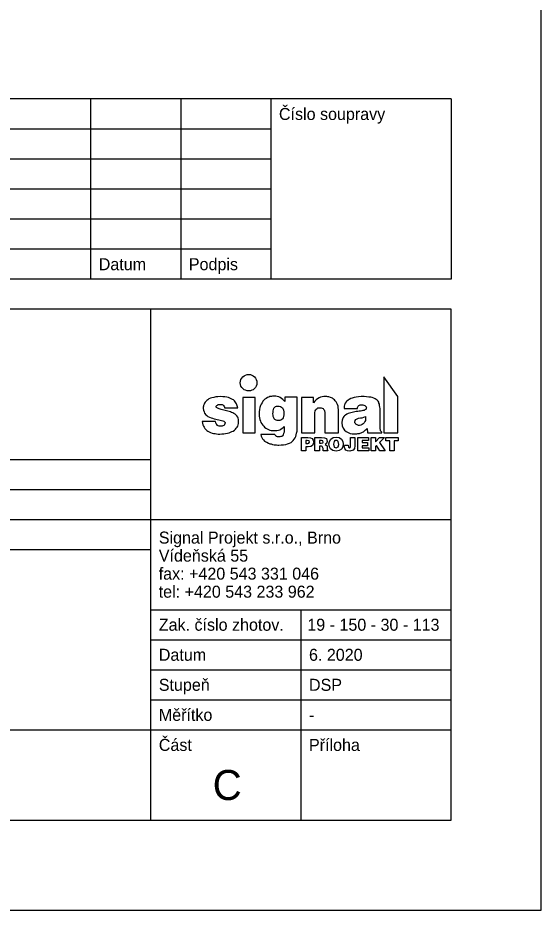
# Model space of a CAD drawing. Extents: x -790471 to -790261, y -985260 to -984963.
# Drawn here: x -790347.7 to -790260.6, y -985259.6 to -985111.1 of the extents above; entities that cross this region are included whole.
import ezdxf

# ---------------------------------------------------------------- set-up
doc = ezdxf.new("R2010")
doc.units = 0
for name, color, linetype in [('Info o rozpiskách', 7, 'Continuous'), ('popis', 7, 'Continuous'), ('Ramečky', 7, 'Continuous'), ('Rámečky-tisk', 7, 'Continuous'), ('Text', 7, 'Continuous'), ('Text barevný', 7, 'Continuous')]:
    doc.layers.add(name, color=color, linetype=linetype)

msp = doc.modelspace()

# ---------------------------------------------------------------- linework, layer by layer
at = {"layer": 'Info o rozpiskách'}
for points in [[(-790309.25, -985170.46), (-790308.98, -985170.47), (-790308.76, -985170.57), (-790308.54, -985170.7), (-790308.29, -985170.87), (-790308.15, -985171.07), (-790308.03, -985171.31), (-790307.94, -985171.58), (-790307.92, -985171.84), (-790307.94, -985172.1), (-790308.03, -985172.38), (-790308.15, -985172.62), (-790308.29, -985172.79), (-790308.54, -985172.99), (-790308.76, -985173.09), (-790308.98, -985173.18), (-790309.25, -985173.2), (-790309.54, -985173.18), (-790309.79, -985173.09), (-790310.05, -985172.99), (-790310.23, -985172.79), (-790310.4, -985172.62), (-790310.57, -985172.38), (-790310.65, -985172.1), (-790310.7, -985171.84), (-790310.65, -985171.58), (-790310.57, -985171.31), (-790310.4, -985171.07), (-790310.23, -985170.87), (-790310.05, -985170.7), (-790309.79, -985170.57), (-790309.54, -985170.47), (-790309.25, -985170.46)], [(-790300.48, -985180.94), (-790299.41, -985180.94), (-790299, -985180.98), (-790298.7, -985181.13), (-790298.52, -985181.37), (-790298.46, -985181.72), (-790298.65, -985182.25), (-790298.95, -985182.42), (-790299.38, -985182.47), (-790299.75, -985182.47), (-790299.75, -985183.16), (-790300.48, -985183.16), (-790300.48, -985180.94)], [(-790299.75, -985181.44), (-790299.75, -985181.95), (-790299.43, -985181.95), (-790299.25, -985181.89), (-790299.15, -985181.69), (-790299.23, -985181.52), (-790299.54, -985181.44), (-790299.75, -985181.44)], [(-790298.24, -985180.94), (-790297.16, -985180.94), (-790296.67, -985180.98), (-790296.35, -985181.13), (-790296.19, -985181.58), (-790296.3, -985181.93), (-790296.56, -985182.12), (-790296.24, -985182.34), (-790296.19, -985182.71), (-790296.19, -985182.88), (-790296.17, -985183.05), (-790296.11, -985183.11), (-790296.11, -985183.16), (-790296.86, -985183.16), (-790296.9, -985182.77), (-790297.03, -985182.42), (-790297.18, -985182.4), (-790297.4, -985182.38), (-790297.51, -985182.38), (-790297.51, -985183.16), (-790298.24, -985183.16), (-790298.24, -985180.94)], [(-790297.51, -985181.44), (-790297.51, -985181.89), (-790297.19, -985181.89), (-790296.93, -985181.82), (-790296.88, -985181.69), (-790296.95, -985181.52), (-790297.16, -985181.44), (-790297.51, -985181.44)], [(-790294.73, -985180.89), (-790294.23, -985180.96), (-790293.84, -985181.22), (-790293.63, -985181.59), (-790293.56, -985182.02), (-790293.63, -985182.49), (-790293.85, -985182.86), (-790294.23, -985183.12), (-790294.73, -985183.22), (-790295.25, -985183.12), (-790295.65, -985182.84), (-790295.83, -985182.47), (-790295.91, -985182.02), (-790295.83, -985181.58), (-790295.61, -985181.22), (-790295.23, -985180.96), (-790294.73, -985180.89)], [(-790294.73, -985181.43), (-790294.92, -985181.46), (-790295.05, -985181.58), (-790295.16, -985182.04), (-790295.05, -985182.53), (-790294.73, -985182.68), (-790294.38, -985182.49), (-790294.28, -985182.08), (-790294.4, -985181.61), (-790294.53, -985181.46), (-790294.73, -985181.43)], [(-790292.33, -985180.94), (-790291.6, -985180.94), (-790291.6, -985182.32), (-790291.67, -985182.75), (-790291.88, -985183.05), (-790292.46, -985183.22), (-790292.83, -985183.18), (-790293.11, -985183.03), (-790293.29, -985182.75), (-790293.37, -985182.36), (-790293.35, -985182.19), (-790292.7, -985182.19), (-790292.66, -985182.56), (-790292.51, -985182.68), (-790292.38, -985182.6), (-790292.33, -985182.42), (-790292.33, -985180.94)], [(-790291.13, -985180.94), (-790289.32, -985180.94), (-790289.32, -985181.44), (-790290.4, -985181.44), (-790290.4, -985181.78), (-790289.49, -985181.78), (-790289.49, -985182.3), (-790290.4, -985182.3), (-790290.4, -985182.64), (-790289.27, -985182.64), (-790289.27, -985183.16), (-790291.13, -985183.16), (-790291.13, -985180.94)], [(-790288.91, -985180.94), (-790288.16, -985180.94), (-790288.16, -985181.65), (-790287.53, -985180.94), (-790286.67, -985180.94), (-790287.49, -985181.78), (-790286.58, -985183.16), (-790287.46, -985183.16), (-790288, -985182.28), (-790288.16, -985182.45), (-790288.16, -985183.16), (-790288.91, -985183.16), (-790288.91, -985180.94)], [(-790286.47, -985180.94), (-790284.41, -985180.94), (-790284.41, -985181.52), (-790285.07, -985181.52), (-790285.07, -985183.16), (-790285.8, -985183.16), (-790285.8, -985181.52), (-790286.47, -985181.52), (-790286.47, -985180.94)]]:
    msp.add_lwpolyline(points, dxfattribs=at)
at = {"layer": 'popis'}
for points in [[(-790286.77, -985170.87), (-790286.77, -985180.14), (-790284.45, -985180.14), (-790284.45, -985174.11), (-790286.77, -985170.87)], [(-790313.29, -985176.02), (-790311.09, -985176.02), (-790311.15, -985175.83), (-790311.19, -985175.66), (-790311.24, -985175.49), (-790311.32, -985175.33), (-790311.41, -985175.18), (-790311.52, -985175.01), (-790311.63, -985174.86), (-790311.8, -985174.69), (-790311.97, -985174.6), (-790312.17, -985174.49), (-790312.4, -985174.39), (-790312.66, -985174.3), (-790312.94, -985174.24), (-790313.26, -985174.19), (-790313.61, -985174.15), (-790314, -985174.13), (-790314.4, -985174.15), (-790314.77, -985174.19), (-790315.09, -985174.26), (-790315.4, -985174.32), (-790315.66, -985174.41), (-790315.89, -985174.52), (-790316.07, -985174.65), (-790316.26, -985174.78), (-790316.43, -985174.93), (-790316.54, -985175.08), (-790316.65, -985175.23), (-790316.71, -985175.4), (-790316.78, -985175.59), (-790316.82, -985175.75), (-790316.86, -985175.89), (-790316.86, -985176.09), (-790316.8, -985176.39), (-790316.71, -985176.69), (-790316.62, -985176.91), (-790316.43, -985177.15), (-790316.26, -985177.28), (-790316.06, -985177.45), (-790315.81, -985177.56), (-790315.55, -985177.64), (-790315.29, -985177.73), (-790315.03, -985177.81), (-790314.77, -985177.88), (-790314.51, -985177.96), (-790314.25, -985177.99), (-790314.02, -985178.03), (-790313.8, -985178.09), (-790313.59, -985178.18), (-790313.39, -985178.25), (-790313.29, -985178.33), (-790313.22, -985178.42), (-790313.2, -985178.52), (-790313.24, -985178.68), (-790313.29, -985178.76), (-790313.33, -985178.85), (-790313.44, -985178.93), (-790313.57, -985179), (-790313.67, -985179.04), (-790313.8, -985179.08), (-790313.93, -985179.08), (-790314.06, -985179.08), (-790314.21, -985179.04), (-790314.38, -985178.98), (-790314.47, -985178.93), (-790314.6, -985178.8), (-790314.69, -985178.68), (-790314.77, -985178.5), (-790314.82, -985178.27), (-790317.01, -985178.27), (-790316.97, -985178.57), (-790316.9, -985178.83), (-790316.8, -985179.06), (-790316.69, -985179.24), (-790316.56, -985179.43), (-790316.41, -985179.6), (-790316.24, -985179.77), (-790316.06, -985179.9), (-790315.83, -985180.01), (-790315.61, -985180.12), (-790315.38, -985180.2), (-790315.14, -985180.27), (-790314.86, -985180.29), (-790314.62, -985180.34), (-790314.38, -985180.36), (-790314.06, -985180.36), (-790313.74, -985180.34), (-790313.43, -985180.34), (-790313.13, -985180.29), (-790312.83, -985180.23), (-790312.55, -985180.18), (-790312.31, -985180.08), (-790312.06, -985179.95), (-790311.86, -985179.86), (-790311.65, -985179.73), (-790311.47, -985179.56), (-790311.34, -985179.41), (-790311.2, -985179.24), (-790311.09, -985179.06), (-790311.02, -985178.83), (-790311, -985178.61), (-790311, -985178.39), (-790311, -985178.33), (-790311, -985178.27), (-790311, -985178.22), (-790311, -985178.16), (-790311, -985178.09), (-790311, -985178.03), (-790311, -985177.99), (-790311, -985177.96), (-790311.02, -985177.71), (-790311.11, -985177.53), (-790311.24, -985177.34), (-790311.39, -985177.21), (-790311.54, -985177.08), (-790311.73, -985176.93), (-790311.9, -985176.84), (-790312.12, -985176.76), (-790312.32, -985176.69), (-790312.55, -985176.61), (-790312.77, -985176.54), (-790312.98, -985176.5), (-790313.22, -985176.44), (-790313.43, -985176.39), (-790313.65, -985176.35), (-790313.84, -985176.3), (-790314.02, -985176.22), (-790314.19, -985176.18), (-790314.32, -985176.11), (-790314.45, -985176.07), (-790314.53, -985176.02), (-790314.64, -985175.94), (-790314.67, -985175.89), (-790314.67, -985175.81), (-790314.67, -985175.74), (-790314.64, -985175.66), (-790314.56, -985175.59), (-790314.49, -985175.55), (-790314.41, -985175.47), (-790314.28, -985175.47), (-790314.13, -985175.44), (-790314, -985175.44), (-790313.85, -985175.44), (-790313.72, -985175.47), (-790313.61, -985175.49), (-790313.5, -985175.55), (-790313.43, -985175.64), (-790313.39, -985175.74), (-790313.31, -985175.85), (-790313.29, -985176.02)], [(-790303.24, -985174.24), (-790303.24, -985174.97), (-790303.41, -985174.77), (-790303.59, -985174.6), (-790303.8, -985174.43), (-790304.04, -985174.28), (-790304.28, -985174.17), (-790304.51, -985174.11), (-790304.75, -985174.08), (-790305.03, -985174.06), (-790305.29, -985174.08), (-790305.48, -985174.09), (-790305.74, -985174.13), (-790305.93, -985174.23), (-790306.15, -985174.28), (-790306.35, -985174.43), (-790306.58, -985174.54), (-790306.76, -985174.73), (-790306.91, -985174.92), (-790307.06, -985175.16), (-790307.19, -985175.4), (-790307.29, -985175.64), (-790307.4, -985175.96), (-790307.47, -985176.3), (-790307.51, -985176.67), (-790307.51, -985177.06), (-790307.51, -985177.38), (-790307.47, -985177.66), (-790307.4, -985177.92), (-790307.32, -985178.2), (-790307.23, -985178.44), (-790307.1, -985178.68), (-790306.93, -985178.89), (-790306.78, -985179.08), (-790306.62, -985179.24), (-790306.45, -985179.39), (-790306.22, -985179.52), (-790306, -985179.62), (-790305.78, -985179.71), (-790305.53, -985179.77), (-790305.29, -985179.8), (-790305.03, -985179.8), (-790304.81, -985179.8), (-790304.6, -985179.77), (-790304.34, -985179.73), (-790304.12, -985179.64), (-790303.91, -985179.54), (-790303.7, -985179.41), (-790303.56, -985179.28), (-790303.39, -985179.09), (-790303.39, -985179.64), (-790303.39, -985180.03), (-790303.46, -985180.29), (-790303.56, -985180.49), (-790303.63, -985180.64), (-790303.76, -985180.75), (-790303.91, -985180.79), (-790304.08, -985180.85), (-790304.26, -985180.85), (-790304.36, -985180.85), (-790304.49, -985180.83), (-790304.6, -985180.79), (-790304.69, -985180.75), (-790304.75, -985180.68), (-790304.84, -985180.61), (-790304.86, -985180.53), (-790304.9, -985180.44), (-790307.27, -985180.44), (-790307.21, -985180.74), (-790307.1, -985180.94), (-790306.97, -985181.17), (-790306.84, -985181.33), (-790306.67, -985181.54), (-790306.45, -985181.65), (-790306.24, -985181.74), (-790306, -985181.89), (-790305.78, -985181.97), (-790305.53, -985182.02), (-790305.31, -985182.08), (-790305.05, -985182.14), (-790304.84, -985182.15), (-790304.66, -985182.17), (-790304.43, -985182.19), (-790304.26, -985182.19), (-790303.85, -985182.17), (-790303.46, -985182.14), (-790303.09, -985182.08), (-790302.79, -985182.01), (-790302.49, -985181.91), (-790302.23, -985181.78), (-790302.03, -985181.63), (-790301.86, -985181.44), (-790301.69, -985181.24), (-790301.56, -985181.02), (-790301.45, -985180.77), (-790301.35, -985180.49), (-790301.32, -985180.2), (-790301.22, -985179.86), (-790301.22, -985179.51), (-790301.22, -985179.09), (-790301.22, -985174.24), (-790303.24, -985174.24)], [(-790300.5, -985174.26), (-790300.5, -985180.14), (-790298.26, -985180.14), (-790298.26, -985177.14), (-790298.26, -985176.82), (-790298.2, -985176.52), (-790298.11, -985176.35), (-790298.03, -985176.2), (-790297.9, -985176.11), (-790297.75, -985176.03), (-790297.57, -985176.02), (-790297.38, -985175.98), (-790297.19, -985176.02), (-790297.06, -985176.05), (-790296.9, -985176.11), (-790296.8, -985176.22), (-790296.73, -985176.35), (-790296.65, -985176.52), (-790296.62, -985176.78), (-790296.62, -985177.04), (-790296.62, -985180.14), (-790294.34, -985180.14), (-790294.34, -985176.59), (-790294.34, -985176.28), (-790294.36, -985175.98), (-790294.41, -985175.7), (-790294.51, -985175.44), (-790294.6, -985175.21), (-790294.71, -985175.01), (-790294.88, -985174.84), (-790294.99, -985174.67), (-790295.14, -985174.54), (-790295.31, -985174.41), (-790295.5, -985174.36), (-790295.68, -985174.26), (-790295.91, -985174.19), (-790296.09, -985174.15), (-790296.28, -985174.11), (-790296.5, -985174.11), (-790296.78, -985174.11), (-790297.06, -985174.19), (-790297.31, -985174.23), (-790297.57, -985174.36), (-790297.81, -985174.49), (-790298.05, -985174.67), (-790298.26, -985174.92), (-790298.5, -985175.18), (-790298.5, -985174.26), (-790300.5, -985174.26)], [(-790293.41, -985176.11), (-790291.19, -985176.11), (-790291.17, -985175.94), (-790291.13, -985175.81), (-790291.06, -985175.72), (-790290.96, -985175.64), (-790290.85, -985175.57), (-790290.7, -985175.53), (-790290.57, -985175.53), (-790290.42, -985175.53), (-790290.25, -985175.53), (-790290.09, -985175.55), (-790289.96, -985175.62), (-790289.88, -985175.66), (-790289.81, -985175.74), (-790289.73, -985175.81), (-790289.73, -985175.9), (-790289.69, -985176), (-790289.73, -985176.09), (-790289.75, -985176.2), (-790289.84, -985176.28), (-790289.94, -985176.35), (-790290.07, -985176.43), (-790290.25, -985176.46), (-790290.46, -985176.5), (-790290.66, -985176.54), (-790290.89, -985176.56), (-790291.13, -985176.59), (-790291.36, -985176.63), (-790291.6, -985176.67), (-790291.84, -985176.73), (-790292.08, -985176.76), (-790292.29, -985176.84), (-790292.51, -985176.87), (-790292.74, -985176.97), (-790292.96, -985177.08), (-790293.15, -985177.23), (-790293.31, -985177.32), (-790293.44, -985177.47), (-790293.54, -985177.62), (-790293.61, -985177.71), (-790293.67, -985177.88), (-790293.7, -985178.03), (-790293.74, -985178.2), (-790293.76, -985178.35), (-790293.76, -985178.52), (-790293.7, -985179), (-790293.56, -985179.39), (-790293.31, -985179.73), (-790293.05, -985179.93), (-790292.74, -985180.12), (-790292.38, -985180.25), (-790292.06, -985180.33), (-790291.73, -985180.34), (-790291.58, -985180.34), (-790291.45, -985180.33), (-790291.3, -985180.33), (-790291.13, -985180.29), (-790291.02, -985180.27), (-790290.85, -985180.25), (-790290.7, -985180.21), (-790290.57, -985180.18), (-790290.44, -985180.1), (-790290.31, -985180.03), (-790290.18, -985179.97), (-790290.03, -985179.88), (-790289.92, -985179.78), (-790289.81, -985179.67), (-790289.66, -985179.56), (-790289.55, -985179.47), (-790289.51, -985180.16), (-790287.12, -985180.16), (-790287.12, -985180.06), (-790287.25, -985179.93), (-790287.31, -985179.84), (-790287.36, -985179.75), (-790287.36, -985179.67), (-790287.4, -985179.56), (-790287.4, -985179.49), (-790287.4, -985179.37), (-790287.4, -985179.23), (-790287.4, -985176.35), (-790287.4, -985176.11), (-790287.46, -985175.87), (-790287.49, -985175.64), (-790287.53, -985175.42), (-790287.59, -985175.23), (-790287.64, -985175.08), (-790287.74, -985174.92), (-790287.9, -985174.75), (-790288.07, -985174.62), (-790288.24, -985174.51), (-790288.46, -985174.39), (-790288.71, -985174.3), (-790288.97, -985174.24), (-790289.3, -985174.21), (-790289.66, -985174.17), (-790290.07, -985174.11), (-790290.53, -985174.13), (-790291.02, -985174.17), (-790291.37, -985174.23), (-790291.73, -985174.28), (-790292.05, -985174.37), (-790292.29, -985174.47), (-790292.53, -985174.6), (-790292.74, -985174.73), (-790292.92, -985174.88), (-790293.05, -985175.03), (-790293.2, -985175.2), (-790293.28, -985175.38), (-790293.31, -985175.53), (-790293.37, -985175.72), (-790293.41, -985175.9), (-790293.41, -985176.11)], [(-790310.27, -985174.26), (-790310.27, -985180.14), (-790308.18, -985180.14), (-790308.18, -985174.26), (-790310.27, -985174.26)], [(-790304.39, -985175.7), (-790304.19, -985175.74), (-790303.98, -985175.79), (-790303.8, -985175.89), (-790303.65, -985176.02), (-790303.56, -985176.2), (-790303.48, -985176.41), (-790303.41, -985176.67), (-790303.41, -985176.95), (-790303.41, -985177.19), (-790303.48, -985177.42), (-790303.54, -985177.64), (-790303.63, -985177.81), (-790303.74, -985177.92), (-790303.91, -985178.05), (-790304.08, -985178.11), (-790304.3, -985178.12), (-790304.53, -985178.11), (-790304.71, -985178.05), (-790304.9, -985177.92), (-790305.01, -985177.83), (-790305.1, -985177.64), (-790305.2, -985177.47), (-790305.23, -985177.25), (-790305.25, -985177.01), (-790305.23, -985176.74), (-790305.2, -985176.5), (-790305.16, -985176.28), (-790305.09, -985176.07), (-790304.99, -985175.94), (-790304.82, -985175.79), (-790304.64, -985175.74), (-790304.39, -985175.7)], [(-790289.81, -985177.47), (-790289.81, -985177.49), (-790289.81, -985177.55), (-790289.81, -985177.58), (-790289.84, -985177.84), (-790289.86, -985178.11), (-790289.96, -985178.29), (-790290.07, -985178.52), (-790290.22, -985178.68), (-790290.4, -985178.78), (-790290.61, -985178.87), (-790290.81, -985178.93), (-790290.98, -985178.93), (-790291.09, -985178.89), (-790291.21, -985178.83), (-790291.32, -985178.78), (-790291.43, -985178.7), (-790291.52, -985178.61), (-790291.6, -985178.52), (-790291.62, -985178.37), (-790291.58, -985178.12), (-790291.45, -985177.94), (-790291.22, -985177.83), (-790290.98, -985177.75), (-790290.66, -985177.68), (-790290.38, -985177.64), (-790290.09, -985177.55), (-790289.81, -985177.47)]]:
    msp.add_lwpolyline(points, dxfattribs=at)
at = {"layer": 'Ramečky'}
for p, q in [((-790275.59, -985124.6), (-790455.59, -985124.6)), ((-790335.59, -985124.6), (-790335.59, -985154.6)), ((-790320.59, -985124.6), (-790320.59, -985154.6)), ((-790305.59, -985124.6), (-790305.59, -985154.6)), ((-790275.59, -985124.6), (-790275.59, -985154.6)), ((-790305.59, -985129.6), (-790455.59, -985129.6)), ((-790305.59, -985134.6), (-790455.59, -985134.6)), ((-790305.59, -985139.6), (-790455.59, -985139.6)), ((-790305.59, -985144.6), (-790455.59, -985144.6)), ((-790305.59, -985149.6), (-790455.59, -985149.6)), ((-790275.59, -985154.6), (-790455.59, -985154.6)), ((-790275.59, -985159.6), (-790455.59, -985159.6)), ((-790325.59, -985244.6), (-790325.59, -985159.6)), ((-790275.59, -985244.6), (-790275.59, -985159.6)), ((-790455.59, -985184.6), (-790325.59, -985184.6)), ((-790455.59, -985189.6), (-790325.59, -985189.6)), ((-790455.59, -985194.6), (-790325.59, -985194.6)), ((-790455.59, -985199.6), (-790325.59, -985199.6)), ((-790325.59, -985209.6), (-790275.59, -985209.6)), ((-790325.59, -985214.6), (-790275.59, -985214.6)), ((-790325.59, -985219.6), (-790275.59, -985219.6)), ((-790325.59, -985224.6), (-790275.59, -985224.6)), ((-790455.59, -985229.6), (-790275.59, -985229.6)), ((-790455.59, -985244.6), (-790275.59, -985244.6))]:
    msp.add_line(p, q, dxfattribs=at)
for points in [[(-790325.59, -985194.6), (-790275.59, -985194.6)], [(-790300.59, -985209.6), (-790300.59, -985244.6)]]:
    msp.add_lwpolyline(points, dxfattribs=at)
at = {"layer": 'Rámečky-tisk'}
msp.add_lwpolyline([(-790470.59, -985259.6), (-790260.59, -985259.6), (-790260.59, -984962.6)], dxfattribs=at)

# ---------------------------------------------------------------- texts
at = {"layer": 'Text'}
for s, p in [('Číslo soupravy', (-790304.24, -985128.1)), ('Datum', (-790334.24, -985153.1)), ('Podpis', (-790319.24, -985153.1)), ('Signal Projekt s.r.o., Brno', (-790324.24, -985198.6)), ('Vídeňská 55', (-790324.24, -985201.6)), ('fax: +420 543 331 046', (-790324.26, -985204.6)), ('tel: +420 543 233 962', (-790324.26, -985207.6)), ('Zak. číslo zhotov.', (-790324.24, -985213.1)), ('19 - 150 - 30 - 113', (-790299.52, -985213.1)), ('Datum', (-790324.24, -985218.1)), ('6. 2020', (-790299.24, -985218.1)), ('Stupeň', (-790324.24, -985223.1)), ('DSP', (-790299.24, -985223.1)), ('Měřítko', (-790324.24, -985228.1)), ('-', (-790299.24, -985228.1)), ('Část', (-790324.24, -985233.1)), ('Příloha', (-790299.24, -985233.1))]:
    msp.add_text(s, height=2, dxfattribs=at).set_placement(p)
at = {"layer": 'Text barevný'}
msp.add_text('C', height=5, dxfattribs=at).set_placement((-790315.27, -985241.27))

doc.saveas('drawing.dxf')
